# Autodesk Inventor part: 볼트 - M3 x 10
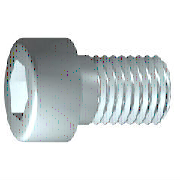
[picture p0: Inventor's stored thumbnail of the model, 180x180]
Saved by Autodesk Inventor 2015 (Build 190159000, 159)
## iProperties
Created: 2012-02
Part Number: 볼트 - M3 x 10
Material: 스테인리스강
Description: 6각 소켓 머리 캡 나사
Document SubType Name: Modeling
Standard: ISO 4762
Designer: mduedu
Standard Revision: Fourth edition 2004-03-01
Standards Organization: ISO
Language: ko-KR
Size Designation: M3 x 10
Categories: <MemberInstance><Categories><Category DisplayName="조임쇠" InternalName="e4da775c-781d-43d5-af7c-5136215cf5a6" Mnemonic="FSTN"><Category DisplayName="볼트" InternalN
Density: 8.08 g/cm^3
Mass: 1.0701 g
Surface Area: 2.01851 cm^2
Volume: 0.132438 cm^3
Appearance: 반광택
IsCustomPart: 0
Author: mduedu
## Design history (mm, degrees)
sketch "스케치1"
  geometry: L1 (-0.867, 0)-(10, 0); L2 (10, 0)-(10, 1.5); L3 (10, 1.5)-(1.25, 1.5); L4 (1.25, 1.5)-(0.943, 1.5); L5 (0.943, 1.5)-(0, 1.5); L6 (0, 1.5)-(0, 2.75); L7 (0, 2.75)-(-3, 2.75); L8 (-3, 2.75)-(-3, 1.443); L9 (-3, 1.443)-(-1.7, 1.443); L10 (-1.7, 1.443)-(-0.867, 0); L11 (-5.6, 0)-(12.6, 0) reference; L12 (0, -0.55)-(0, 3.3) reference; L13 (1.25, 1.5)-(0, 1.5)
  constraints: 22 end point, 6 parallel, 2 collinear, 2 perpendicular, 1 horizontal, 1 point on line
  dimensions: "d1" = 8.75 distance from line of L3.end L2 (= GEL); "d2" = 0.30683 distance of L4.end L3.end (computed from GAL); "d3" = 3 distance between parallel lines of L8 L6 (= KOH); "d4" = 1.3 distance of L8.end L9.end (= INTI); "d5" = 60 deg angle of L10 L1; "d6" = 3 diameter of L3 L1 (= GD); "d7" = 3 diameter of L5 L1 (= BDM); "d8" = 2.88675 diameter of L9 L1 (= 1.1547 x SW); "d9" = 5.5 diameter of L7 L1 (= KOD); "d26" = 10 distance between parallel lines of L12 L2 (= NLG)
revolve "본체" sketch "스케치1" stored, may be unused: angle "d10" = 90 deg
sketch "스케치2"
  geometry: L1 (0, -3.85)-(0, 3.85) reference; L2 (-3.85, 0)-(3.85, 0) reference; L3 (1.443, 0)-(0.722, -1.25); L4 (0.722, -1.25)-(-0.722, -1.25); L5 (-0.722, -1.25)-(-1.443, 0); L6 (-1.443, 0)-(-0.722, 1.25); L7 (-0.722, 1.25)-(0.722, 1.25); L8 (0.722, 1.25)-(1.443, 0); 2 further points
  constraints: 12 end point, 1 coincident, 1 horizontal alignment, 1 point on line, 12 other
extrude "슬롯" join sketch "스케치2" stored distance "d11" = 10; taper "d12" = 0 deg
workplane "Work Plane1"
fillet "Fillet2" dims "d30" = 0.1 (= R)
body "Solid1"
fillet "모깎기1" dims "d17" = 0.3 (= RR)
feature "스레드" dims "d13" = 8.75 (= GEL), "d14" = 0
chamfer "모따기1" distance "d15" = 0.30673 (= -0.5 x SPD + 0.5 x GD); stored, may be unused: second distance "d16" = 0.30673 (= GUL), angle "d27" = 45 deg
other parameters: "GD" = 3 [user parameter; used in 2 equation terms], "NLG" = 10 [user parameter; used in 1 equation term], "GEL" = 8.75 [user parameter; used in 2 equation terms], "KOD" = 5.5 [user parameter; used in 1 equation term], "KOH" = 3 [user parameter; used in 1 equation term], "INTI" = 1.3 [user parameter; used in 1 equation term], "GAL" = 0.30673 (= 0.61345 x PTC) [user parameter; used in 1 equation term], "GUL" = 0.30673 (= 0.61345 x PTC) [user parameter; used in 1 equation term], "BDM" = 3 (= NND) [user parameter; used in 1 equation term], "SW" = 2.5 [user parameter; used in 2 equation terms], "RR" = 0.3 [user parameter; used in 1 equation term], "SPD" = 2.38655 (= NND - 1.2269 x PTC) [user parameter; used in 1 equation term], "d19" = 0, "d28" = 0, "d29" = 0, "R" = 0.1 [user parameter; used in 1 equation term], "TOA" = 30 deg [user parameter], "GD1" = 2.38655 (= THREADDIA - 1.2269 x PTC) [user parameter], "THREADDIA" = 3 [user parameter; used in 1 equation term], "FAWI" = 45 deg [user parameter], "PTC" = 0.5 [user parameter; used in 5 equation terms], "NND" = 3 [user parameter; used in 2 equation terms], "E0" = 2.8875 (= 1.155 x SW) [user parameter]
